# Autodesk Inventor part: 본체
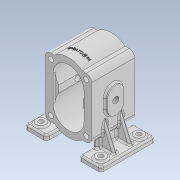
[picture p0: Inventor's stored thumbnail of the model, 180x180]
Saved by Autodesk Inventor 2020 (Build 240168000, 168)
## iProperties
Created: 2023-06
Part Number: 본체
Material: 일반
Document SubType Name: Modeling
Designer: oem
Density: 1 g/cm^3
Appearance: 기본값
Author: oem
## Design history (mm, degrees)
sketch "스케치1"
  geometry: L1 (-32.5, 55)-(32.5, 55); L2 (42.5, 45)-(42.5, -45); L3 (32.5, -55)-(-32.5, -55); L4 (-42.5, -45)-(-42.5, 45); L5 (-42.5, 55)-(42.5, -55); L6 (42.5, 55)-(-42.5, -55); L7 (-32.5, 45)-(32.5, 45); L8 (32.5, 45)-(32.5, -45); L9 (32.5, -45)-(-32.5, -45); L10 (-32.5, -45)-(-32.5, 45); L11 (-32.5, 45)-(32.5, -45); L12 (32.5, 45)-(-32.5, -45); C1 r 4.5 at (-32.5, 45); C2 r 4.5 at (32.5, 45); C3 r 4.5 at (32.5, -45); C4 r 4.5 at (-32.5, -45); A1 r 10 centre (-32.5, 45) between (-32.5, 55) and (-42.5, 45); A2 r 10 centre (32.5, 45) between (42.5, 45) and (32.5, 55); A3 r 10 centre (32.5, -45) between (32.5, -55) and (42.5, -45); A4 r 10 centre (-32.5, -45) between (-42.5, -45) and (-32.5, -55); 1 further point
  constraints: 24 end point, 8 centre point, 8 point on circle, 8 point on line, 8 tangent, 4 coincident, 4 midpoint, 4 parallel, 3 equal radius, 2 horizontal, 2 perpendicular
  dimensions: "d0" = 85 distance of L5.end L6.end; "d1" = 110 distance of L6.start L5.end; "d2" = 10 radius of A1; "d3" = 65 distance of L8.end L9.end; "d4" = 90 distance of L7.end L8.end; "d5" = 9 diameter of C1; "d6" = 9 diameter of C2; "d7" = 9 diameter of C3; "d8" = 9 diameter of C4
extrude "돌출1" new body sketch "스케치1" distance "d9" = 79; taper "d10" = 0 deg
sketch "스케치2"
  geometry: L1 (32.5, 55)-(-32.5, 55) reference; A1 r 40 centre (0, 24) between (-25.278, 55) and (25.278, 55); A2 r 40 centre (0, 24) between (25.278, 55) and (-25.278, 55); 1 further point
  constraints: 4 point on circle, 2 centre point, 2 point on line, 1 vertical alignment
  dimensions: "d11" = 80 diameter of A1; "d12" = 24 distance of point (0, 0) A1.centre
extrude "돌출2" join sketch "스케치2" distance "d13" = 79; taper "d14" = 0 deg
node "작업 평면1"
sketch "스케치3"
  geometry: L1 (-42.5, 0)-(-42.5, 79) reference; L2 (25.278, 79)-(-25.278, 79) reference; L3 (70, -10.5)-(30, -10.5); L4 (-70, -10.5)-(-70, 89.5); L5 (-70, 89.5)-(-30, 89.5); L6 (70, 89.5)-(70, -10.5); L7 (70, -10.5)-(-70, 89.5); L8 (-70, -10.5)-(70, 89.5); L9 (-30, -10.5)-(-30, 89.5); L10 (-30, -10.5)-(-70, -10.5); L11 (-30, 89.5)-(30, 89.5); L12 (30, -10.5)-(30, 89.5); L13 (30, -10.5)-(-30, -10.5); L14 (30, 89.5)-(70, 89.5); 6 further points
  constraints: 24 end point, 10 parallel, 8 perpendicular, 6 midpoint, 3 horizontal, 1 horizontal alignment, 1 vertical alignment
  dimensions: "d16" = 140 distance of L4.end L6.start; "d17" = 100 distance of L4.start L4.end; "d18" = 40 distance between parallel lines of L4 L9; "d19" = 40 distance between parallel lines of L12 L6
extrude "돌출3" join sketch "스케치3" distance "d20" = 9; taper "d21" = 0 deg
sketch "스케치4"
  geometry: L1 (30, 10.5)-(30, -89.5) reference; L2 (30, -14.5)-(38, -14.5); L3 (38, -14.5)-(38, -64.5); L4 (38, -64.5)-(30, -64.5); L5 (30, -64.5)-(30, -14.5); 3 further points
  constraints: 8 end point, 2 midpoint, 2 parallel, 1 horizontal, 1 perpendicular, 1 point on line
  dimensions: "d22" = 8 distance of L3.end L4.end; "d23" = 50 distance of L2.end L3.end
extrude "돌출4" join sketch "스케치4" stored distance "d24" = 9; taper "d25" = 0 deg
sketch "스케치5"
  geometry: L1 (0, 0)-(0, 90) reference; L2 (0, 0)-(-79, 0) reference; L3 (-39.5, 54)-(-39.5, 36); L4 (-54.5, 54)-(-54.5, 36); L5 (-24.5, 36)-(-24.5, 54); A1 r 15 centre (-39.5, 54) between (-24.5, 54) and (-54.5, 54); A2 r 15 centre (-39.5, 36) between (-54.5, 36) and (-24.5, 36); 4 further points
  constraints: 8 end point, 4 point on circle, 4 tangent, 3 midpoint, 2 centre point, 1 horizontal alignment, 1 parallel, 1 vertical, 1 vertical alignment
  dimensions: "d26" = 30 diameter of A2; "d27" = 48 dimension on A2 A1
sketch "스케치6"
  geometry: L1 (70, -89.5)-(70, 10.5) reference; L2 (55, -4.5)-(55, -74.5); C1 r 9 at (55, -74.5); C2 r 9 at (55, -4.5); 3 further points
  constraints: 2 centre point, 2 end point, 2 midpoint, 1 horizontal alignment, 1 vertical, 1 vertical alignment
  dimensions: "d28" = 15 distance from line of L1 L2.end; "d29" = 18 diameter of C1; "d30" = 18 diameter of C2; "d31" = 70 distance of L2.start L2.end
extrude "돌출5" join sketch "스케치6" distance "d32" = 3; taper "d33" = 0 deg
sketch "스케치7"
  geometry: C1 r 9 at (0, 0) reference; C2 r 9 at (0, 70) reference; 3 further points
  constraints: 2 coincident
hole "구멍1" sketch "스케치7" at (0, 0), (0, 70) diameter "d34" = 9; stored, may be unused: countersink angle "d38" = 90 deg, drill point angle "d40" = 118 deg; dims "d35" = 6, "d36" = 4, "d37" = 2, "d39" = 8
node "작업 평면3"
  node "작업 평면2"
sketch "스케치8"
  geometry: L1 (70, -71)-(30, -71) reference; L2 (70, -80)-(70, -71) reference; L3 (42.5, -45)-(42.5, 45) reference; L4 (62, -71)-(39.578, -18.177); 1 further point
  constraints: 2 end point, 1 point on line
  dimensions: "d46" = 8 distance from line of L2 L4.start; "d47" = 23 deg angle of L2 L4
feature "리브1" sketch "스케치8" dims "d48" = 1, "d49" = 7, "d50" = 0, "d51" = 0, "d52" = 1, "d53" = 1
node "작업 평면4"
node "작업 평면5"
sketch "스케치9"
  geometry: L1 (70, -10.5)-(70, 89.5) reference; L2 (70, 39.5)-(-70, 39.5); L3 (-70, 89.5)-(-70, -10.5) reference; 2 further points
  constraints: 2 end point, 2 midpoint, 1 vertical alignment, 1 other
  dimensions: "d55" = 20 distance from line of point (0, 59.5) L2
feature "엠보싱1" sketch "스케치9" dims "d3" = 65, "d4" = 90, "d5" = 9, "d6" = 9, "d7" = 9, "d8" = 9, "d56" = 0.5, "d57" = 0
sketch "스케치10"
  geometry: L1 (-42.5, 45)-(-42.5, -45) reference; L2 (22.5, 6.507)-(22.5, -6.507); L3 (-22.5, -6.507)-(-22.5, 6.507); L4 (-22.5, 0)-(22.5, 0); A1 r 40 centre (0, -24) between (-25.278, -55) and (25.278, -55) reference; A2 r 28.5 centre (0, -24) between (-22.5, -6.507) and (22.5, -6.507); A3 r 40 centre (0, 24) between (1.526, 63.971) and (-2.042, 63.948) reference; A4 r 28.5 centre (0, 24) between (22.5, 6.507) and (-22.5, 6.507); 2 further points
  constraints: 6 end point, 4 midpoint, 4 point on circle, 2 centre point, 2 coincident, 1 horizontal alignment, 1 parallel
  dimensions: "d58" = 57 diameter of A2; "d59" = 57 diameter of A4; "d62" = 45 distance between parallel lines of L2 L3; "d63" = 42.5 distance from line of point (0, 0) L1
extrude "돌출6" cut sketch "스케치10" extent not by distance; stored distance "d64" = 0; taper "d65" = 0 deg
sketch "스케치12"
  geometry: L1 (45, 79)-(-45, 79) reference; L2 (24, 79)-(-24, 79); L3 (-24, 79)-(-24, 74.5); L4 (-24, 74.5)-(24, 74.5); L5 (24, 74.5)-(24, 79); 4 further points
  constraints: 8 end point, 2 midpoint, 2 parallel, 1 horizontal, 1 perpendicular, 1 point on line, 1 vertical alignment
  dimensions: "d66" = 48 distance of L4.end L3.end; "d67" = 4.5 distance of L2.end L3.end
extrude "돌출7" cut sketch "스케치12" stored distance "d68" = 57; taper "d69" = 0 deg
node "작업 평면6"
fillet "모깎기1" dims "d70" = 5
fillet "모깎기2" dims "d71" = 3
fillet "모깎기3" dims "d72" = 3
fillet "모깎기6" dims "d75" = 3
fillet "모깎기7" dims "d76" = 3
fillet "모깎기8" dims "d77" = 3
fillet "모깎기9" dims "d78" = 3
fillet "모깎기10" dims "d79" = 3
fillet "모깎기11" dims "d80" = 3
fillet "모깎기12" dims "d81" = 3
fillet "모깎기13" dims "d82" = 3
fillet "모깎기14" dims "d83" = 3
extrude "돌출8" join sketch "스케치5" distance "d84" = 5; taper "d85" = 0 deg
sketch "스케치13"
  geometry: L1 (-24.5, 36)-(-24.5, 54) reference; A1 r 15 centre (-39.5, 54) between (-24.5, 54) and (-54.5, 54) reference; 3 further points
  constraints: 1 horizontal alignment, 1 midpoint, 1 vertical alignment
hole "구멍2" sketch "스케치13" at (-39.5, 45) diameter "d86" = 10.5; stored, may be unused: countersink angle "d92" = 90 deg, drill point angle "d94" = 118 deg; dims "d87" = 11, "d88" = 0.62479, "d89" = 10.589, "d90" = 4, "d91" = 2, "d93" = 17.5
fillet "모깎기15" dims "d95" = 3
fillet "모깎기16" dims "d96" = 3
node "솔리드1"
mirror "미러1"
mirror "미러2"
mirror "미러3"
mirror "미러4"
mirror "미러5"
mirror "미러6"
mirror "미러8"
mirror "미러9"
feature "A9D066F2-1C7D-4E18-AEED-F7BC21143FA4" dims "d34" = 9, "d35" = 6, "d36" = 4, "d37" = 2, "d38" = 90 deg, "d39" = 8, "d40" = 118 deg
other parameters: "d41" = 11
